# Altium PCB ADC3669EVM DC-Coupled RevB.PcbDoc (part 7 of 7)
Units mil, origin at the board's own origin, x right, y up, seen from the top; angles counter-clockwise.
Board outline 5000 x 2716.54 mil, 12 copper layers (Top Layer, L2 GND, L3 SIG, L4 GND, L5 PWR, L6 GND, L7 GND, L8 PWR, L9 GND, L10 PWR, L11 GND, Bottom Layer), stack 61 mil thick; 546 components, 341 nets, 2088 pads, 1256 vias.
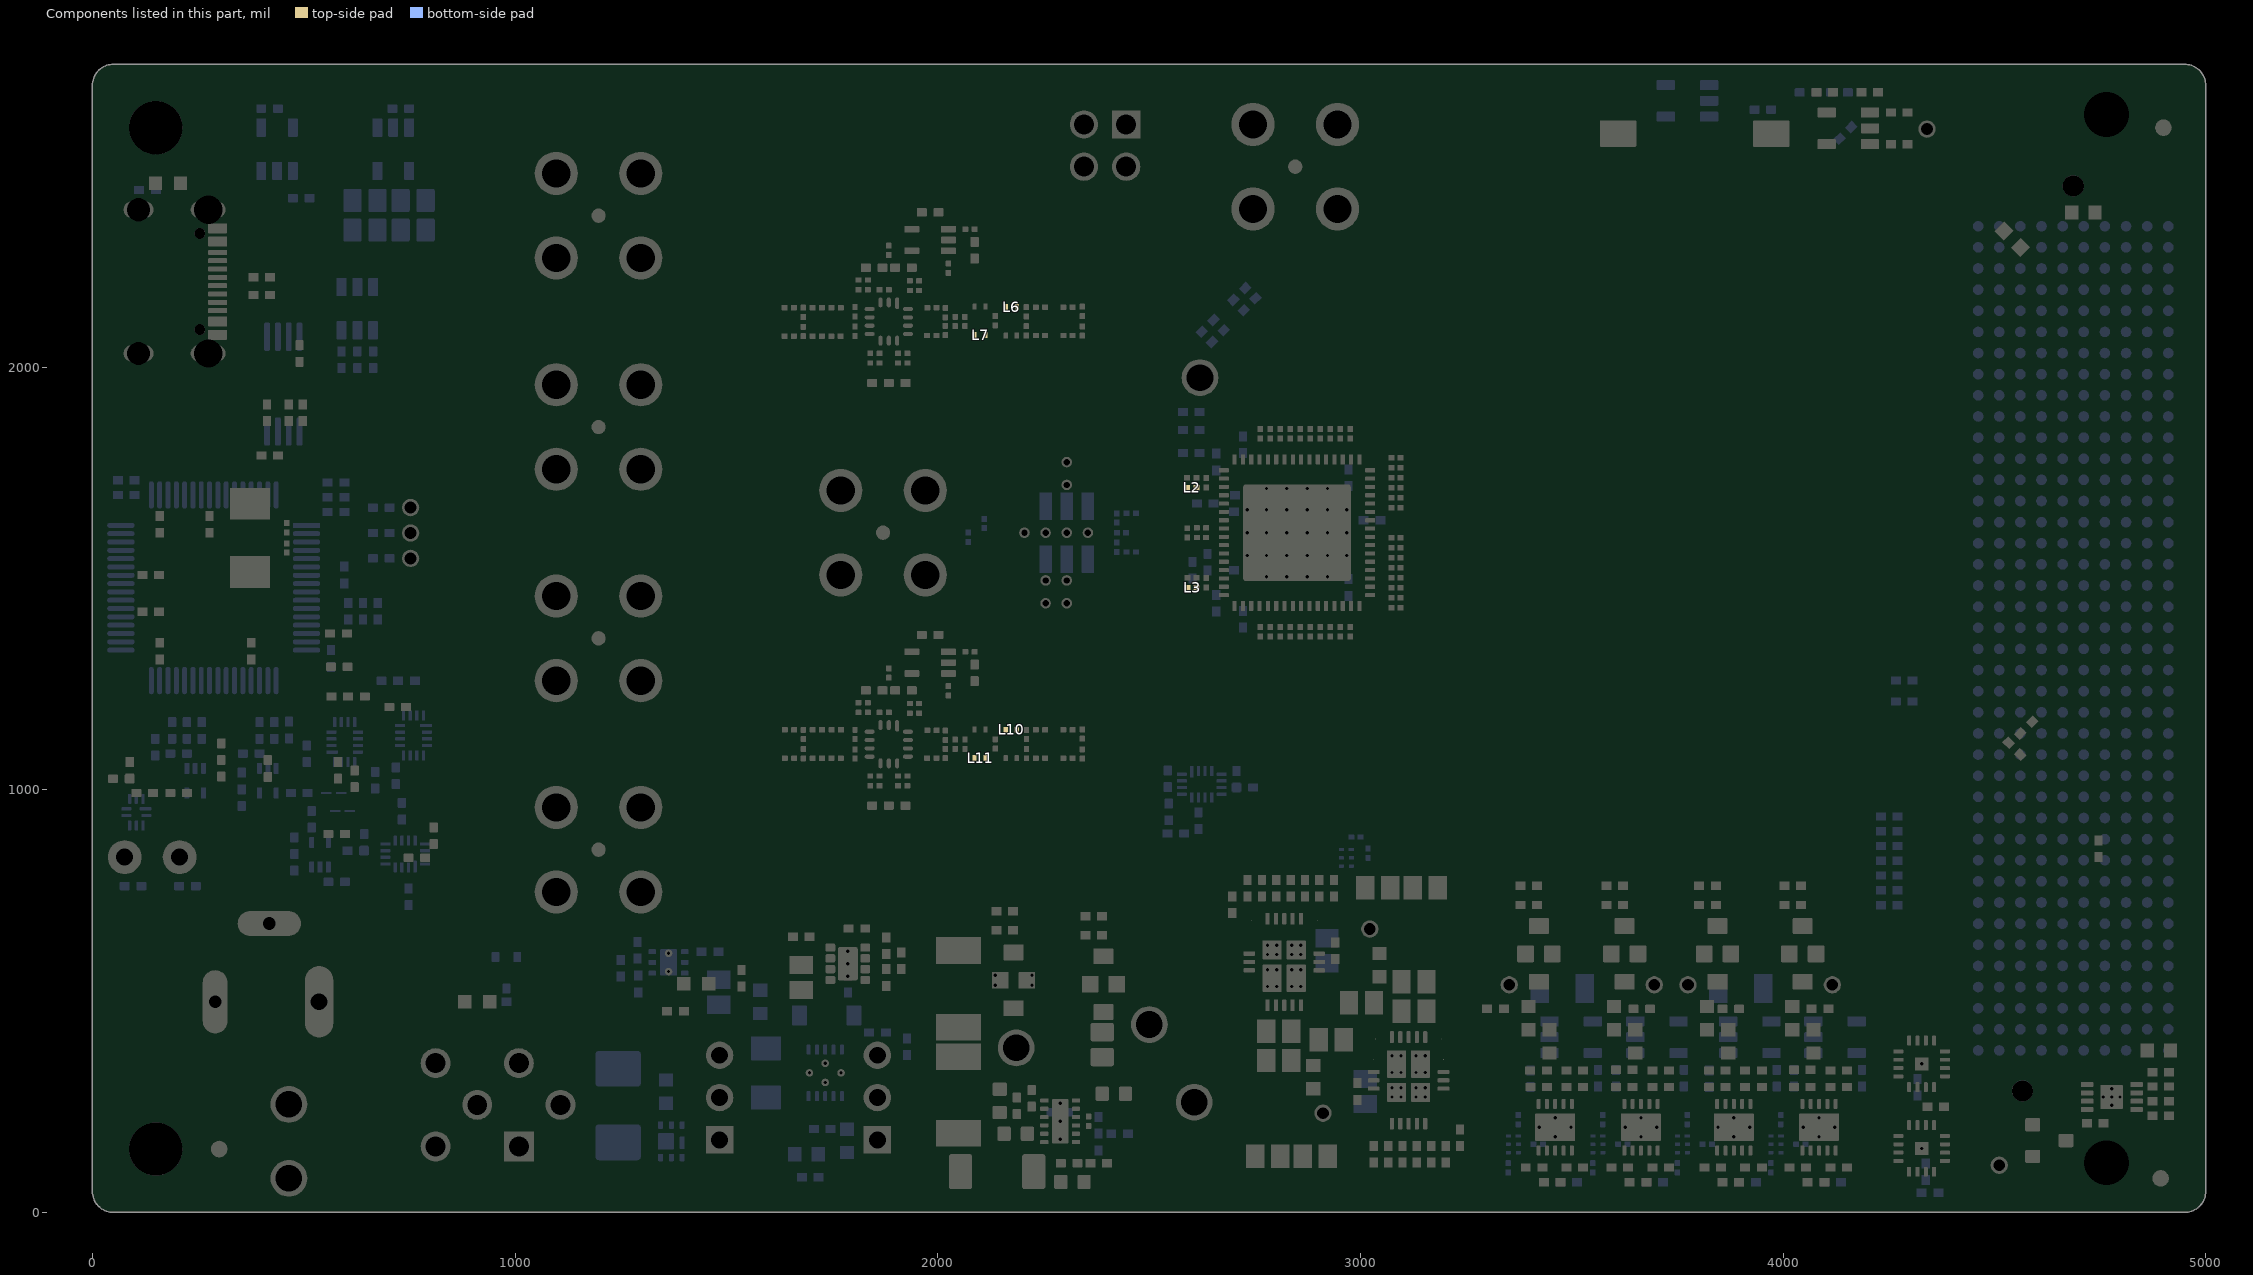
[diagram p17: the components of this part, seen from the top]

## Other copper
Top Layer:
  drawing of 104 lines, arcs and shapes, not listed
  text ".Layer_Name" at 577,-858.49 h60
L2 GND:
  pour cut-out: 1197.57,883.99 ccw(c1197.5,858.27) 1179.31,876.46 ccw(c1196.84,858.93) 1172.05,858.93 1172.05,857.55 ccw(c1196.78,857.55) 1179.3,840.07 1180.01,839.36 ccw(c1197.5,856.85) 1197.5,832.11 1198.2,832.11 ccw(c1198.2,857.57) 1216.2,839.57 1216.34,839.71 ccw(c1198,858.05) 1223.94,858.05 ccw(c1198.01,858.05) 1216.35,876.38 1215.98,876.75 ccw(c1198.5,859.27) 1198.5,883.99
  pour cut-out: 1197.57,1383.99 ccw(c1197.5,1358.27) 1179.31,1376.46 ccw(c1196.84,1358.93) 1172.05,1358.93 1172.05,1357.55 ccw(c1196.78,1357.55) 1179.3,1340.07 1180.01,1339.36 ccw(c1197.5,1356.85) 1197.5,1332.11 1198.2,1332.11 ccw(c1198.2,1357.57) 1216.2,1339.57 1216.34,1339.71 ccw(c1198,1358.05) 1223.94,1358.05 ccw(c1198.01,1358.05) 1216.35,1376.38 1215.98,1376.75 ccw(c1198.5,1359.27) 1198.5,1383.99
  pour cut-out: 1197.57,2383.99 ccw(c1197.5,2358.27) 1179.31,2376.46 ccw(c1196.84,2358.93) 1172.05,2358.93 1172.05,2357.55 ccw(c1196.78,2357.55) 1179.3,2340.07 1180.01,2339.36 ccw(c1197.5,2356.85) 1197.5,2332.11 1198.2,2332.11 ccw(c1198.2,2357.57) 1216.2,2339.57 1216.34,2339.71 ccw(c1198,2358.05) 1223.94,2358.05 ccw(c1198.01,2358.05) 1216.35,2376.38 1215.98,2376.75 ccw(c1198.5,2359.27) 1198.5,2383.99
  pour cut-out: 1197.57,1883.99 ccw(c1197.5,1858.27) 1179.31,1876.46 ccw(c1196.84,1858.93) 1172.05,1858.93 1172.05,1857.55 ccw(c1196.78,1857.55) 1179.3,1840.07 1180.01,1839.36 ccw(c1197.5,1856.85) 1197.5,1832.11 1198.2,1832.11 ccw(c1198.2,1857.57) 1216.2,1839.57 1216.34,1839.71 ccw(c1198,1858.05) 1223.94,1858.05 ccw(c1198.01,1858.05) 1216.35,1876.38 1215.98,1876.75 ccw(c1198.5,1859.27) 1198.5,1883.99
  text ".Layer_Name" at 572,-863.49 h60
L3 SIG:
  pour cut-out: 1197.57,2383.99 ccw(c1197.5,2358.27) 1179.31,2376.46 ccw(c1196.84,2358.93) 1172.05,2358.93 1172.05,2357.55 ccw(c1196.78,2357.55) 1179.3,2340.07 1180.01,2339.36 ccw(c1197.5,2356.85) 1197.5,2332.11 1198.2,2332.11 ccw(c1198.2,2357.57) 1216.2,2339.57 1216.34,2339.71 ccw(c1198,2358.05) 1223.94,2358.05 ccw(c1198.01,2358.05) 1216.35,2376.38 1215.98,2376.75 ccw(c1198.5,2359.27) 1198.5,2383.99
  pour cut-out: 1197.57,883.99 ccw(c1197.5,858.27) 1179.31,876.46 ccw(c1196.84,858.93) 1172.05,858.93 1172.05,857.55 ccw(c1196.78,857.55) 1179.3,840.07 1180.01,839.36 ccw(c1197.5,856.85) 1197.5,832.11 1198.2,832.11 ccw(c1198.2,857.57) 1216.2,839.57 1216.34,839.71 ccw(c1198,858.05) 1223.94,858.05 ccw(c1198.01,858.05) 1216.35,876.38 1215.98,876.75 ccw(c1198.5,859.27) 1198.5,883.99
  pour cut-out: 1197.57,1383.99 ccw(c1197.5,1358.27) 1179.31,1376.46 ccw(c1196.84,1358.93) 1172.05,1358.93 1172.05,1357.55 ccw(c1196.78,1357.55) 1179.3,1340.07 1180.01,1339.36 ccw(c1197.5,1356.85) 1197.5,1332.11 1198.2,1332.11 ccw(c1198.2,1357.57) 1216.2,1339.57 1216.34,1339.71 ccw(c1198,1358.05) 1223.94,1358.05 ccw(c1198.01,1358.05) 1216.35,1376.38 1215.98,1376.75 ccw(c1198.5,1359.27) 1198.5,1383.99
  pour cut-out: 1197.57,1883.99 ccw(c1197.5,1858.27) 1179.31,1876.46 ccw(c1196.84,1858.93) 1172.05,1858.93 1172.05,1857.55 ccw(c1196.78,1857.55) 1179.3,1840.07 1180.01,1839.36 ccw(c1197.5,1856.85) 1197.5,1832.11 1198.2,1832.11 ccw(c1198.2,1857.57) 1216.2,1839.57 1216.34,1839.71 ccw(c1198,1858.05) 1223.94,1858.05 ccw(c1198.01,1858.05) 1216.35,1876.38 1215.98,1876.75 ccw(c1198.5,1859.27) 1198.5,1883.99
  text ".Layer_Name" at 582,-858.49 h60
L6 GND:
  text ".Layer_Name" at 577,-863.49 h60
L7 GND:
  text ".Layer_Name" at 582,-863.49 h60
L10 PWR:
  pour cut-out: 2375.68,1583.41 2375.68,1507.41 2334.68,1507.41 2334.68,1583.41
  pour cut-out: 2375.68,1708.61 2375.68,1632.61 2334.68,1632.61 2334.68,1708.61
  pour cut-out: 2275.68,1708.61 2275.68,1632.61 2234.68,1632.61 2234.68,1708.61
  text ".Layer_Name" at 587,-863.49 h60
L11 GND:
  pour cut-out: 2375.68,1583.41 2375.68,1507.41 2334.68,1507.41 2334.68,1583.41
  pour cut-out: 2375.68,1708.61 2375.68,1632.61 2334.68,1632.61 2334.68,1708.61
  pour cut-out: 2275.68,1708.61 2275.68,1632.61 2234.68,1632.61 2234.68,1708.61
  text ".Layer_Name" at 582,-848.49 h60
Bottom Layer:
  region net 5V: 751,2361.04 750.68,2234.1 628.58,2234.1 ccw(c628.58,2206.78) 602.43,2214.71 602.43,2202.59 cw(c589.45,2202.59) 601.26,2197.19 601.26,2170.7 cw(c598.5,2170.7) 598.5,2167.95 580.43,2167.95 cw(c580.43,2170.75) 577.63,2170.75 577.63,2267.14 cw(c589.45,2267.14) 589.45,2278.95 627.12,2278.95 ccw(c627.12,2304.53) 652.69,2304.53 652.69,2416.96 cw(c657.47,2416.96) 657.47,2421.73 ccw(c657.47,2426.8) 662.54,2426.8 662.54,2483.23 cw(c665.13,2483.23) 665.13,2485.83 683.4,2485.83 cw(c683.4,2483.07) 686.16,2483.07 686.16,2448.08 ccw(c712.5,2448.08) 712.5,2421.73 746.82,2421.73 cw(c746.83,2417.56) 751,2417.56
  region net VCORE: 145.38,1723.44 ccw(c138.9,1723.44) 138.9,1729.92 ccw(c138.9,1724.59) 133.57,1724.59 133.57,1723.49 cw(c117.39,1723.49) 117.39,1707.31 88.3,1707.31 88.3,1687.62 116.18,1687.62 cw(c116.18,1670.19) 133.61,1670.19 ccw(c138.82,1670.19) 138.82,1664.99 139.57,1664.99 ccw(c139.57,1670.8) 145.38,1670.8 145.38,1672.03
  region net GND: 1416.52,120.79 ccw(c1416.52,124.73) 1420.45,124.73 1420.45,180.61 ccw(c1415.8,180.61) 1415.8,185.26 1397.41,185.26 ccw(c1397.41,177.37) 1389.52,177.37 1389.52,129.58 1389.48,129.58 1389.48,123.86 ccw(c1392.54,123.86) 1392.54,120.79
  region net GND: 1644.7,120.67 1682.33,120.67 ccw(c1682.33,127.81) 1689.48,127.81 1689.48,147.73 ccw(c1683.03,147.73) 1683.03,154.13 1644.7,154.13
  region net GND: 1802.04,125.17 1802.04,162.8 ccw(c1794.9,162.8) 1794.9,169.94 1774.99,169.94 ccw(c1774.99,163.5) 1768.58,163.5 1768.58,125.17
  region net GND: 1843.23,442.16 1799.98,442.16 cw(c1799.98,446.1) 1796.04,446.1 1796.04,486.17 cw(c1799.64,486.17) 1799.64,490.19 1843.23,490.19
  region net 1p8V_Utility: 1239.95,546.31 1239.95,569.52 1239.63,569.84 1239.79,570 1242.74,569.93 1272.98,569.93 ccw(c1272.98,571.9) 1274.95,571.9 1324.79,571.9 1331.7,571.9 cw(c1331.7,569.95) 1333.65,569.95 1333.65,562.03 cw(c1331.7,562.03) 1331.7,560.08 1312.45,560.08 ccw(c1312.45,554.79) 1307.15,554.79 cw(c1300.64,554.79) 1300.64,548.27 1261.6,548.27 ccw(c1261.6,546.31) 1259.63,546.31
  region net MainPwr: 1509.49,559.86 1510.13,560.5 1619.61,560.5 1619.61,626.05 1619.77,626.2 1619.14,626.83 1469.12,626.83 1469.12,583.67 cw(c1457.29,583.67) 1458.49,571.9 1401.56,571.9 1394.65,571.9 ccw(c1394.65,569.95) 1392.7,569.95 1392.7,562.03 ccw(c1394.65,562.03) 1394.65,560.08 1409.59,560.08 cw(c1409.59,550.24) 1419.43,550.24 1419.43,543.16 ccw(c1434,543.15) 1434,528.59 1509.49,528.59
  region net NetF2_1: 1044.43,191.72 1044.43,104.43 965,25 657.93,25 532.93,150 447.72,150 398.54,199.18 398.54,563.64 448.13,613.23 615.09,613.23 703.35,524.97 703.35,142.62 748.06,97.91 876.41,97.91 970.22,191.72 980.26,191.72
  region net GND: 2565.6,1017.07 2589.22,1017.07 2589.22,1040.69 2565.6,1040.69 2565.6,1022.32
  region net VADJ: 775.62,820.51 799.24,820.51 799.24,844.13 775.62,844.13 775.62,825.75
  region net VADJ: 775.62,836.26 799.24,836.26 799.24,859.88 775.62,859.88 775.62,841.5
  region net 3p3V_Utility: 585.07,1077.32 585.07,1053.7 608.69,1053.7 608.69,1077.32 590.31,1077.32
  region net 3p3V_Utility: 569.32,1077.32 569.32,1053.7 592.94,1053.7 592.94,1077.32 574.57,1077.32
  region net NetC2_2: 890.19,413.44 765.73,413.44 763.32,415.86 763.32,215.14 1088.49,215.14 1182.48,121.15 1372.56,121.15 1375.72,124.31 1375.72,274.06 1178.53,274.06 1160,292.59 890.98,292.59
  region net NetC2_1: 922.5,414 922.5,312.51 1181.03,312.51 1196.05,297.5 1379.68,297.5 1389.5,287.68 1389.5,197.92 1421.45,197.92 1421.45,300.48 1442.88,321.9 1527.55,321.9 1535.52,329.87 1535.52,400.36 1521,414
  region net NetF1_2: 1627.93,300.48 1641.5,286.9 1738.53,286.9 1738.53,264.76 1718.79,245.02 1718.79,187.41 1695.16,187.41 1651.84,230.74 1456.25,230.74 1437.1,249.89 1437.1,292.59 1454.51,310 1525.03,309.92 1534.46,300.48
  region net NetC3_2: 1748.83,281.94 1748.85,281.93 1748.85,256.92 1733.87,241.94 1734.53,241.27 1734.53,187.77 1701.27,154.5 1701.27,97.91 1706.33,92.84 1706.33,73.16 1729.81,73.16 1732.76,76.11 1732.76,154.5 1758.16,179.89 1758.16,281.74 1758.28,281.86
  region net NetC4_2: 1768.52,284.03 1769.48,283.06 1769.48,180.36 1800.67,180.36 1800.98,180.66 1800.98,243.73 1777.96,266.75 1777.96,283.57
  region net NetD4_1: 1641.93,373.64 1627.87,359.58 1558.17,359.58 1558.17,489.91 1738.53,489.91 1738.53,373.64
  pour cut-out: 2375.68,1708.61 2375.68,1632.61 2334.68,1632.61 2334.68,1708.61
  pour cut-out: 2275.68,1708.61 2275.68,1632.61 2234.68,1632.61 2234.68,1708.61
  pour cut-out: 2375.68,1583.41 2375.68,1507.41 2334.68,1507.41 2334.68,1583.41
  text ".Layer_Name" at 577,-858.49 h60
Multi-Layer:
  pour cut-out: 1870.66,1633.99 ccw(c1870.59,1608.27) 1852.4,1626.46 ccw(c1869.93,1608.93) 1845.14,1608.93 1845.14,1607.55 ccw(c1869.87,1607.55) 1852.38,1590.07 1853.09,1589.36 ccw(c1870.59,1606.85) 1870.59,1582.11 1871.29,1582.11 ccw(c1871.29,1607.57) 1889.29,1589.57 1889.43,1589.71 ccw(c1871.09,1608.05) 1897.03,1608.05 ccw(c1871.1,1608.05) 1889.43,1626.38 1889.07,1626.75 ccw(c1871.59,1609.27) 1871.59,1633.99

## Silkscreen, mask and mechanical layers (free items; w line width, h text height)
Top Overlay:
  circle w10: c3034.96,1816.84 r4.89
  text "ADC3669EVM-DC / DC-Coupled / LMH5401 / Rev B" at 3456.09,1774.18 h60
  text "12V 1A" at 35.49,328.46 h50
  text ".Layer_Name" at 577,-858.49 h60
Bottom Overlay:
  text "VCM" at 2550.34,1951.27 h50
  text "12V / FMC" at 4661.42,46.52 h40
  text ".Layer_Name" at 577,-858.49 h60
Top Paste:
  text ".Layer_Name" at 577,-858.49 h60
Bottom Paste:
  text ".Layer_Name" at 577,-858.49 h60
Top Solder:
  text ".Layer_Name" at 577,-858.49 h60
  text ".Layer_Name" at 577,-858.49 h60
Bottom Solder:
  text ".Layer_Name" at 577,-858.49 h60
Drill Guide:
  text ".Layer_Name" at 577,-858.49 h60
M1 Board Outline:
  lines w10: 0,50 ccw(c50,50) 50,0 4950,0 ccw(c4950,50) 5000,50 5000,2616.53 5000,2666.54 ccw(c4950,2666.54) 4950,2716.54 50,2716.54 ccw(c50,2666.54) 0,2666.54 ; 0,50 0,50 ; 0,50 0,2666.53 ; 0,2666.53 0,2666.54
  text ".Layer_Name" at 577,-858.49 h60
M2 Board Dimensions:
  rectangle: 125,-400 500,-275
  rectangle: 0,-275 125,-150
  lines w7: 0,-275 1000,-275 ; 125,-400 125,-150 ; 250,-400 250,-150 ; 500,-400 500,-150 ; 750,-400 750,-150 ; 0,-400 0,-150 1000,-150 1000,-400 0,-400
  text ".Layer_Name" at 577,-858.49 h60
M3 3D STEP Top:
  text ".Layer_Name" at 577,-858.49 h60
M4 3D STEP Bottom:
  text ".Layer_Name" at 577,-858.49 h60
M5 Assembly Top:
  circle w10: c1616.28,1894.8 r4
  lines w10: -292,-930.17 6308,-930.17 ; -292,-726.83 6310,-726.83 ; -292,-523.5 -292,-1133.5 3713,-1133.5 6310,-1133.5 6310,-523.5 -291.5,-523.5 -291.5,-1133.5 1284,-1133.5 ; 2173,-1133.5 2173,-523.5 ; 3440,-726.83 3440,-523.5 ; 4280,-726.83 4280,-523.5 ; 4902,-1140 4902,-937.17
  text "COMPONENTS MARKED 'DNP' SHOULD NOT BE POPULATED." at 1153.5,-318.5 h60
  text "ASSEMBLY VARIANT:" at 1153,-434 h60
  text ".VariantName" at 2189,-434 h60
  text "PCB VIEWED FROM TOP SIDE" at -228.5,-655.67 h60
  text "BOARD #:" at 2248,-655.67 h60
  text ".PRJ_Number" at 2793.5,-655.67 h60
  text "REV:" at 3638,-655.67 h60
  text ".PCB_Rev" at 3929.5,-655.67 h60
  text "SVN REV:" at 4476,-655.67 h60
  text ".VersionControl_RevNumber" at 4982,-655.67 h60
  text "PLOT NAME =" at -228.5,-1064.34 h60
  text ".plot_File_Name" at 577,-1064.34 h60
  text "GENERATED    :" at 2250,-1064.34 h60
  text ".Print_Date" at 3119.5,-1064.34 h60
  text ".Print_Time" at 3848.5,-1064.34 h60
  text "TEXAS INSTRUMENTS" at 5113,-1064.34 h60
M6 Assembly Bottom:
  lines w10: -292.5,-727.33 6309.5,-727.33 ; -290.5,-930.67 6309.5,-930.67 ; 1115.5,-1140.5 1115.5,-937.67 ; 1737.5,-727.33 1737.5,-524 ; 2577.5,-727.33 2577.5,-524 ; 3844.5,-1134 3844.5,-524 ; 4733.5,-1134 6309,-1134 6309,-524 -292.5,-524 -292.5,-1134 2304.5,-1134 6309.5,-1134 6309.5,-524
  text "COMPONENTS MARKED 'DNP' SHOULD NOT BE POPULATED." at 6102,-318 h60
  text ".VariantName" at 5058,-434 h60
  text "ASSEMBLY VARIANT:" at 6097,-434 h60
  text ".VersionControl_RevNumber" at 1035.5,-656.17 h60
  text "SVN REV:" at 1541.5,-656.17 h60
  text ".PCB_Rev" at 2088,-656.17 h60
  text "REV:" at 2379.5,-656.17 h60
  text ".PRJ_Number" at 3224,-656.17 h60
  text "BOARD #:" at 3769.5,-656.17 h60
  text "PCB VIEWED FROM BOTTOM SIDE" at 6246,-656.17 h60
  text "TEXAS INSTRUMENTS" at 904.5,-1064.84 h60
  text ".Print_Time" at 2169,-1064.84 h60
  text ".Print_Date" at 2898,-1064.84 h60
  text "GENERATED    :" at 3767.5,-1064.84 h60
  text ".plot_File_Name" at 5440.5,-1064.84 h60
  text "PLOT NAME =" at 6246,-1064.84 h60
M9 Title Sheet:
  drawing of 56 lines, arcs and shapes, not listed
  text "1" at 1058.34,13381.39 h70
  text "2" at 4384,13381.39 h70
  text "3" at 7714,13381.39 h70
  text "4" at 11049,13381.39 h70
  text "5" at 14374,13381.39 h70
  text "6" at 17709,13381.39 h70
  text "A" at -463,11603.39 h70
  text "A" at 19237,11603.39 h70
  text "B" at -463,7853.39 h70
  text "B" at 19237,7853.39 h70
  text "C" at -463,4103.39 h70
  text "C" at 19237,4103.39 h70
  text "D" at -463,353.39 h70
  text "D" at 19237,353.39 h70
  text "PROJECT TITLE:" at 16143,268.39 h45
  text ".PRJ_Title" at 16193,135.06 h70
  text "DESIGNED FOR:" at 16143,-32.61 h45
  text ".PRJ_Customer" at 16193,-172.61 h70
  text "FILE NAME:" at 16143,-332.61 h45
  text ".PCB_File_Name_No_Path" at 16193,-452.61 h70
  text "Texas Instruments (TI) and/or its licensors do not warrant the accuracy or completeness of this specification" at 11173.5,-614.45 h45
  text "ENGINEER:" at 16143,-622.61 h45
  text "LAYOUT BY:" at 17648,-622.61 h45
  text "or any information contained therein. TI and/or its licensors do not warrant that this design will meet" at 11128.51,-727.11 h45
  text ".PRJ_Engineer" at 16193,-777.6 h70
  text ".PCB_Layout" at 17698.5,-777.6 h70
  text "the specifications, will be suitable for your application or fit for any particular purpose, or will operate in" at 11128.51,-839.78 h45
  text ".Layer_Name" at 577,-858.49 h60
  text "ALTIUM DESIGNER VERSION:" at 17648,-932.61 h45
  text "an implementation. TI and/or its licensors do not warrant that the design is production worthy. You should" at 11128.51,-952.44 h45
  text "completely validate and test your design implementation to confirm the system functionality for your application." at 11173.5,-1065.11 h45
  text ".print_Scale" at 16193,-1065.94 h70
  text ".Application_BuildNumber" at 17698.5,-1065.94 h70
  text "1" at 1058.34,-1318.61 h70
  text "2" at 4384,-1318.61 h70
  text "3" at 7714,-1318.61 h70
  text "4" at 11049,-1318.61 h70
  text "5" at 14374,-1318.61 h70
  text "6" at 17709,-1318.61 h70
M10 Fab Notes:
  drawing of 209 lines, arcs and shapes, not listed
  text "M10 Fab Notes" at 16103.69,8035.93 h60
  text "DESIGN INFORMATION" at 17182.02,7918.81 h60
  text "MIN. TRACK WIDTH:" at 16537.46,7786.68 h60
  text "4" at 17633.7,7786.68 h60
  text "MIL" at 17788.46,7786.68 h60
  text "MIN. CLEARANCE:" at 16537.46,7662.55 h60
  text "MIL" at 17788.46,7662.55 h60
  text "5" at 17633.92,7660.91 h60
  text "MIN. VIA PAD SIZE:" at 16537.46,7538.43 h60
  text "18" at 17603.71,7538.43 h60
  text "MIL" at 17788.46,7538.43 h60
  text "0.05mm (2MIL)" at 17232.46,7408.53 h60
  text "MINIMUM ANNULAR RING" at 16208.23,7400.31 h60
  text "EXTERNAL" at 17940.46,7400.31 h60
  text "PER" at 16408.23,7290.18 h60
  text "IPC-D-275 CLASS 2 LEVEL C" at 16628.23,7290.18 h60
  text "MIL, HOLES" at 18116.46,7189.7 h60
  text "+/-" at 17724,7181.11 h60
  text "+/-" at 18578,7181.11 h60
  text "REGISTRATION TOLERANCES:" at 16208.23,7180.05 h60
  text "METAL" at 17408,7180.05 h60
  text "5" at 17984.2,7180.05 h60
  text "3" at 18817.2,7180.05 h60
  text "MIL" at 18933.46,7180.05 h60
  text "HOLE SIZE TOLERANCE (UNLESS OTHERWISE SPECIFIED):" at 16208.23,7081.73 h60
  text "+/-" at 18578,7078.86 h60
  text "3" at 18817.2,7077.8 h60
  text "MIL" at 18933.46,7077.8 h60
  text "MATERIAL:" at 16133.46,6940.15 h60
  text "UNIFORM STACKUP" at 17867.51,6845.23 h60
  text "HYBRID STACKUP" at 16841.98,6837.95 h60
  text "X" at 17730,6830 h60
  text "FR4-408" at 16548.18,6674.31 h60
  text "X" at 16404,6667.3 h60
  text "Megtron 4    Isola I-Speed" at 16539.43,6473.06 h60
  text "OR" at 16989.42,6473.06 h60
  text "Megtron6    Isola MT-40    Nelco MW-1000" at 16539.43,6276.21 h60
  text "OR" at 16940.78,6276.21 h60
  text "OR" at 17639.51,6276.21 h60
  text "OTHER" at 16579.43,6079.36 h60
  text "X" at 16756.89,5882.87 h60
  text "62 MIL (1.6mm) +/-10%" at 16877.71,5881.78 h60
  text "92 MIL  +/-10%" at 18453.68,5881.78 h60
  text "THICKNESS:" at 16211.38,5873.55 h60
  text "OTHER" at 18162.61,5873.55 h60
  text "TOLERANCE:" at 16211.38,5735.24 h60
  text "X" at 17059.61,5735.24 h60
  text "ANSI IPC-6012 TYPE 3 CLASS 2" at 17237.62,5735.24 h60
  text "OTHER +/-" at 17237.61,5591.05 h60
  text "BOW & TWIST:" at 16211.38,5445.86 h60
  text "X" at 17059.61,5445.86 h60
  text "ANSI IPC-6012 TYPE 3 CLASS 2" at 17237.62,5445.86 h60
  text "OTHER +/-" at 17237.61,5299.17 h60
  text "DRILLING:" at 16136.61,5168.55 h60
  text "NC_DRILL FILES" at 17897.61,5063.36 h60
  text "REFERENCE:" at 16211.38,5059.42 h60
  text "X" at 16868.61,5059.32 h60
  text "AS SHOWN" at 17046.61,5059.42 h60
  text "X" at 17769.61,5059.42 h60
  text "OTHER" at 18195.61,4917.17 h60
  text "PTH COPPER THICKNESS:" at 16211.05,4913.64 h60
  text "X" at 17350.29,4913.64 h60
  text "20-30 um" at 17478.29,4913.64 h60
  text "BOARD FINISH:" at 16136.61,4766.04 h60
  text "SILKSCREEN:" at 16291.83,4655.92 h60
  text "X" at 17249.61,4655.92 h60
  text "TOP" at 17366.61,4655.92 h60
  text "X" at 17759.61,4655.92 h60
  text "BOTTOM" at 17877.61,4655.92 h60
  text "SILKSCREEN COLOR:" at 16291.83,4500.73 h60
  text "X" at 17249.61,4500.73 h60
  text "WHITE" at 17366.61,4500.73 h60
  text "OTHER" at 17877.61,4500.73 h60
  text "RED" at 18483.4,4363.41 h60
  text "X" at 17972.29,4360.69 h60
  text "GREEN" at 17497.61,4357.28 h60
  text "OTHER" at 18115.61,4357.28 h60
  text "SOLDER RESIST COLOR:" at 16291.83,4350.41 h60
  text "X" at 17379.61,4203.03 h60
  text "MATTE" at 17497.61,4203.03 h60
  text "SEMI-GLOSS" at 18115.15,4202.39 h60
  text "X" at 17009.84,4030.26 h60
  text "IMMERSION GOLD (ENIG)" at 17197.61,4030.26 h60
  text "ENEPIG" at 18535.15,4023.03 h60
  text "SURFACE FINISH:" at 16136.61,4022.03 h60
  text "IMM. TIN/SILVER OR EQUIV" at 16466.15,3884.72 h60
  text "HARD GOLD (30u)" at 17897.61,3880.78 h60
  text "OTHER" at 16491.15,3683.93 h60
  text "ARRAY/PANEL:" at 16136.61,3528.55 h60
  text "X" at 17015,3520 h60
  text "CUT AND TRIM PER M1 BOARD OUTLINE" at 17197.61,3520.33 h60
  text "N.C. ROUTE" at 17197.61,3384.36 h60
  text "V. SCORE" at 18063.61,3384.36 h60
  text "CERTIFICATION:" at 16136.61,3255.24 h60
  text "MATERIALS AND WORKMANSHIP FOR ALL PCBS" at 16861.61,3255.24 h60
  text "TO MEET OR EXCEED THE REQUIREMENTS OF:" at 16861.61,3161.18 h60
  text "X" at 16499.12,3032.55 h60
  text "ANSI IPC-A-600F CLASS ->" at 16627.11,3032.55 h60
  text "X" at 18275.12,3032.55 h60
  text "2" at 18385.11,3032.55 h60
  text "1" at 18070.11,3031.05 h60
  text "3" at 18739.11,3031.05 h60
  text "X" at 17311.12,2884.86 h60
  text "RoHS" at 17439.11,2884.86 h60
  text "OTHER" at 18083.51,2884.86 h60
  text "PER ORDER" at 18480.57,2884.86 h60
  text "ALL BOARDS MUST MEET OR EXCEED UL94-V0 REQUIREMENTS." at 16164.15,2731.03 h60
  text "PCB MUST BEAR THE UL94V-0 UL REGISTERED MATERIAL ID NUMBER" at 16164.15,2614.97 h60
  text "ADDITIONAL REQUIREMENTS:" at 16136.61,2445.55 h60
  text "MICROSECTION:" at 16211.38,2338.42 h60
  text "YES" at 17117.11,2338.42 h60
  text "REQUIRED" at 17978.61,2194.09 h60
  text "BARE BOARD ELEC. TEST:" at 16211.38,2191.23 h60
  text "NONE" at 17517.11,2191.23 h60
  text "X" at 17860.61,2191.23 h60
  text "PER ORDER" at 18570.61,2191.23 h60
  text "X" at 16255.91,1999.02 h60
  text "16 MIL & SMALLER VIAS REQUIRE NON-CONDUCTIVE FILL AND PLANARIZE" at 16363.45,1910.22 h59
  text "X" at 16256.89,1799.39 h60
  text "OUTER LAYER TRACKS 9 MIL WIDE REQUIRE 50 OHM SINGLE-ENDED IMPEDANCE" at 16366.4,1699.59 h60
  text "X" at 16255.91,1595.47 h60
  text "OUTER LAYER TRACKS 6 MIL WIDE WITH 4 MIL AIR GAP REQUIRE 100 OHM DIFFERENTIAL IMPEDANCE" at 16366.4,1494.87 h60
  text "INNER LAYER XX & XX TRACKS XX MIL WIDE REQUIRE 50 OHM SINGLE-ENDED IMPEDANCE" at 16366.4,1290.14 h60
  text "INNER LAYER TRACKS XX MIL WIDE WITH   / XX MIL SPACE REQUIRE 100 OHM DIFFERENTIAL IMPEDANCE" at 16360.5,1096.25 h60
  text ".Layer_Name" at 577,-858.49 h60
M11 Gerber Information:
  lines w10: -292,-930.17 6308,-930.17 ; -292,-726.83 6310,-726.83 ; -292,-523.5 -292,-1133.5 3713,-1133.5 6310,-1133.5 6310,-523.5 -291.5,-523.5 -291.5,-1133.5 1284,-1133.5 ; 2173,-1133.5 2173,-523.5 ; 3440,-726.83 3440,-523.5 ; 4280,-726.83 4280,-523.5 ; 4902,-1140 4902,-937.17
  text "ALL ARTWORK VIEWED FROM TOP SIDE" at -228.5,-655.67 h60
  text "BOARD #:" at 2248,-655.67 h60
  text ".PRJ_Number" at 2793.5,-655.67 h60
  text "REV:" at 3638,-655.67 h60
  text ".PCB_Rev" at 3929.5,-655.67 h60
  text "SVN REV:" at 4476,-655.67 h60
  text ".VersionControl_RevNumber" at 4982,-655.67 h60
  text "LAYER NAME =" at -228.5,-858.49 h60
  text "PLOT NAME =" at -228.5,-1064.34 h60
  text ".plot_File_Name" at 577,-1064.34 h60
  text "GENERATED    :" at 2250,-1064.34 h60
  text ".Print_Date" at 3119.5,-1064.34 h60
  text ".Print_Time" at 3848.5,-1064.34 h60
  text "TEXAS INSTRUMENTS" at 5113,-1064.34 h60
M12 Stackup:
  drawing of 763 lines, arcs and shapes, not listed
  text "Layer" at 9956.79,4031.7 h60
  text "Name" at 10366.7,4031.7 h60
  text "Material" at 11296.44,4031.7 h60
  text "Thickness" at 12156.21,4031.7 h60
  text "Constant" at 12806.04,4031.7 h60
  text "Board Layer Stack" at 13375.91,4031.7 h60
  text "Top Overlay" at 10366.7,3911.7 h60
  text "Top Solder" at 10366.7,3791.7 h60
  text "Solder Resist" at 11296.44,3791.7 h60
  text "0.40mil" at 12156.21,3791.7 h60
  text "3.5" at 12806.04,3791.7 h60
  text "1" at 9956.79,3671.7 h60
  text "Top Layer" at 10366.7,3671.7 h60
  text "1.40mil" at 12156.21,3671.7 h60
  text "Dielectric 1" at 10366.7,3551.7 h60
  text "FR408HR" at 11296.44,3551.7 h60
  text "4.50mil" at 12156.21,3551.7 h60
  text "3.54" at 12806.04,3551.7 h60
  text "2" at 9956.79,3431.7 h60
  text "L2 GND" at 10366.7,3431.7 h60
  text "CF-004" at 11296.44,3431.7 h60
  text "1.40mil" at 12156.21,3431.7 h60
  text "Dielectric 3" at 10366.7,3311.7 h60
  text "FR408HR" at 11296.44,3311.7 h60
  text "3.20mil" at 12156.21,3311.7 h60
  text "3.54" at 12806.04,3311.7 h60
  text "3" at 9956.79,3191.7 h60
  text "L3 SIG" at 10366.7,3191.7 h60
  text "CF-004" at 11296.44,3191.7 h60
  text "1.40mil" at 12156.21,3191.7 h60
  text "Dielectric 9" at 10366.7,3071.7 h60
  text "FR408HR" at 11296.44,3071.7 h60
  text "3.20mil" at 12156.21,3071.7 h60
  text "3.54" at 12806.04,3071.7 h60
  text "4" at 9956.79,2951.7 h60
  text "L4 GND" at 10366.7,2951.7 h60
  text "CF-004" at 11296.44,2951.7 h60
  text "1.40mil" at 12156.21,2951.7 h60
  text "Dielectric 7" at 10366.7,2831.7 h60
  text "FR408HR" at 11296.44,2831.7 h60
  text "3.20mil" at 12156.21,2831.7 h60
  text "3.54" at 12806.04,2831.7 h60
  text "5" at 9956.79,2711.7 h60
  text "L5 PWR" at 10366.7,2711.7 h60
  text "CF-004" at 11296.44,2711.7 h60
  text "1.40mil" at 12156.21,2711.7 h60
  text "Dielectric 5" at 10366.7,2591.7 h60
  text "FR408HR" at 11296.44,2591.7 h60
  text "3.20mil" at 12156.21,2591.7 h60
  text "3.54" at 12806.04,2591.7 h60
  text "6" at 9956.79,2471.7 h60
  text "L6 GND" at 10366.7,2471.7 h60
  text "CF-004" at 11296.44,2471.7 h60
  text "1.40mil" at 12156.21,2471.7 h60
  text "Dielectric 11" at 10366.7,2351.7 h60
  text "FR408HR" at 11296.44,2351.7 h60
  text "3.20mil" at 12156.21,2351.7 h60
  text "3.54" at 12806.04,2351.7 h60
  text "Dielectric1" at 10366.7,2231.7 h60
  text "FR408HR" at 11296.44,2231.7 h60
  text "3.20mil" at 12156.21,2231.7 h60
  text "3.54" at 12806.04,2231.7 h60
  text "Dielectric 12" at 10366.7,2111.7 h60
  text "FR408HR" at 11296.44,2111.7 h60
  text "3.20mil" at 12156.21,2111.7 h60
  text "3.54" at 12806.04,2111.7 h60
  text "7" at 9956.79,1991.7 h60
  text "L7 GND" at 10366.7,1991.7 h60
  text "CF-004" at 11296.44,1991.7 h60
  text "1.40mil" at 12156.21,1991.7 h60
  text "Dielectric 6" at 10366.7,1871.7 h60
  text "FR408HR" at 11296.44,1871.7 h60
  text "3.20mil" at 12156.21,1871.7 h60
  text "3.54" at 12806.04,1871.7 h60
  text "8" at 9956.79,1751.7 h60
  text "L8 PWR" at 10366.7,1751.7 h60
  text "CF-004" at 11296.44,1751.7 h60
  text "1.40mil" at 12156.21,1751.7 h60
  text "Dielectric 8" at 10366.7,1631.7 h60
  text "FR408HR" at 11296.44,1631.7 h60
  text "3.20mil" at 12156.21,1631.7 h60
  text "3.54" at 12806.04,1631.7 h60
  text "9" at 9956.79,1511.7 h60
  text "L9 GND" at 10366.7,1511.7 h60
  text "CF-004" at 11296.44,1511.7 h60
  text "1.40mil" at 12156.21,1511.7 h60
  text "Dielectric 10" at 10366.7,1391.7 h60
  text "FR408HR" at 11296.44,1391.7 h60
  text "3.20mil" at 12156.21,1391.7 h60
  text "3.54" at 12806.04,1391.7 h60
  text "10" at 9956.79,1271.7 h60
  text "L10 PWR" at 10366.7,1271.7 h60
  text "CF-004" at 11296.44,1271.7 h60
  text "1.40mil" at 12156.21,1271.7 h60
  text "Dielectric 4" at 10366.7,1151.7 h60
  text "FR408HR" at 11296.44,1151.7 h60
  text "3.20mil" at 12156.21,1151.7 h60
  text "3.54" at 12806.04,1151.7 h60
  text "11" at 9956.79,1031.7 h60
  text "L11 GND" at 10366.7,1031.7 h60
  text "CF-004" at 11296.44,1031.7 h60
  text "1.40mil" at 12156.21,1031.7 h60
  text "Dielectric 2" at 10366.7,911.7 h60
  text "FR408HR" at 11296.44,911.7 h60
  text "4.50mil" at 12156.21,911.7 h60
  text "3.54" at 12806.04,911.7 h60
  text "12" at 9956.79,791.7 h60
  text "Bottom Layer" at 10366.7,791.7 h60
  text "1.40mil" at 12156.21,791.7 h60
  text "Bottom Solder" at 10366.7,671.7 h60
  text "Solder Resist" at 11296.44,671.7 h60
  text "0.40mil" at 12156.21,671.7 h60
  text "3.5" at 12806.04,671.7 h60
  text "Bottom Overlay" at 10366.7,551.7 h60
  text "Total board thickness:" at 9956.79,431.7 h60
  text "61.80mil" at 12156.21,431.7 h60
  text ".Layer_Name" at 577,-858.49 h60
M13 Component Bodies Top:
  text ".Layer_Name" at 577,-858.49 h60
M14 Component Bodies Bottom:
  text ".Layer_Name" at 577,-858.49 h60
M15 Courtyards Top:
  text ".Layer_Name" at 577,-858.49 h60
M16 Courtyards Bottom:
  text ".Layer_Name" at 577,-858.49 h60
Drill Drawing:
  drawing of 185 lines, arcs and shapes, not listed
  text "Symbol" at 230.04,5030 h48
  text "Count" at 577.95,5030 h48
  text "Hole Size" at 1017.84,5030 h48
  text "Plated" at 1790.95,5030 h48
  text "Hole Type" at 2138.86,5030 h48
  text "Drill Layer Pair" at 2638.73,5030 h48
  text "Via/Pad" at 3645.1,5030 h48
  text "Pad Shape" at 4049,5030 h48
  text "Template" at 4782.12,5030 h48
  text "Description" at 5935.11,5030 h48
  text "Hole Tolerance (+)" at 6514.95,5030 h48
  text "Hole Tolerance (-)" at 7414.69,5030 h48
  text "1" at 577.95,4930 h40
  text "39.76mil (1.010mm)" at 1017.84,4930 h40
  text "PTH" at 1790.95,4930 h40
  text "Slot" at 2138.86,4930 h40
  text "Top Layer - Bottom Layer" at 2638.73,4930 h40
  text "Pad" at 3645.1,4930 h40
  text "Rounded" at 4049,4930 h40
  text "r430_170h101_356r85" at 4782.12,4930 h40
  text "2" at 577.95,4830 h40
  text "25.59mil (0.650mm)" at 1017.84,4830 h40
  text "NPTH" at 1790.95,4830 h40
  text "Round" at 2138.86,4830 h40
  text "Top Layer - Bottom Layer" at 2638.73,4830 h40
  text "Pad" at 3645.1,4830 h40
  text "Rounded" at 4049,4830 h40
  text "c65hn65m65p0" at 4782.12,4830 h40
  text "2" at 577.95,4730 h40
  text "29.92mil (0.760mm)" at 1017.84,4730 h40
  text "PTH" at 1790.95,4730 h40
  text "Slot" at 2138.86,4730 h40
  text "Top Layer - Bottom Layer" at 2638.73,4730 h40
  text "Pad" at 3645.1,4730 h40
  text "Rounded" at 4049,4730 h40
  text "r380_150h76_305r75" at 4782.12,4730 h40
  text "2" at 577.95,4630 h40
  text "50.00mil (1.270mm)" at 1017.84,4630 h40
  text "NPTH" at 1790.95,4630 h40
  text "Round" at 2138.86,4630 h40
  text "Top Layer - Bottom Layer" at 2638.73,4630 h40
  text "Pad" at 3645.1,4630 h40
  text "Rounded" at 4049,4630 h40
  text "c127hn127" at 4782.12,4630 h40
  text "2" at 577.95,4530 h40
  text "55.12mil (1.400mm)" at 1017.84,4530 h40
  text "PTH" at 1790.95,4530 h40
  text "Slot" at 2138.86,4530 h40
  text "Top Layer - Bottom Layer" at 2638.73,4530 h40
  text "Pad" at 3645.1,4530 h40
  text "Rounded Rectangle" at 4049,4530 h40
  text "r100_180h140_60r50m100_180p0" at 4782.12,4530 h40
  text "B" at 208.35,4520.01 h44.44
  text "2" at 577.95,4430 h40
  text "66.93mil (1.700mm)" at 1017.84,4430 h40
  text "PTH" at 1790.95,4430 h40
  text "Slot" at 2138.86,4430 h40
  text "Top Layer - Bottom Layer" at 2638.73,4430 h40
  text "Pad" at 3645.1,4430 h40
  text "Rounded Rectangle" at 4049,4430 h40
  text "r100_210h170_60r50m100_210p0" at 4782.12,4430 h40
  text "2" at 577.95,4330 h40
  text "105.91mil (2.690mm)" at 1017.84,4330 h40
  text "NPTH" at 1790.95,4330 h40
  text "Round" at 2138.86,4330 h40
  text "Top Layer - Bottom Layer" at 2638.73,4330 h40
  text "Pad" at 3645.1,4330 h40
  text "Rounded" at 4049,4330 h40
  text "c0hn269m10" at 4782.12,4330 h40
  text "2" at 577.95,4230 h40
  text "125.98mil (3.200mm)" at 1017.84,4230 h40
  text "NPTH" at 1790.95,4230 h40
  text "Round" at 2138.86,4230 h40
  text "Top Layer - Bottom Layer" at 2638.73,4230 h40
  text "Pad" at 3645.1,4230 h40
  text "Rounded" at 4049,4230 h40
  text "c320hn320m320p0" at 4782.12,4230 h40
  text "6" at 577.95,4130 h40
  text "63.00mil (1.600mm)" at 1017.84,4130 h40
  text "PTH" at 1790.95,4130 h40
  text "Round" at 2138.86,4130 h40
  text "Top Layer - Bottom Layer" at 2638.73,4130 h40
  text "Pad" at 3645.1,4130 h40
  text "Rounded" at 4049,4130 h40
  text "c221h160" at 4782.12,4130 h40
  text "8" at 577.95,4030 h40
  text "40.00mil (1.016mm)" at 1017.84,4030 h40
  text "PTH" at 1790.95,4030 h40
  text "Round" at 2138.86,4030 h40
  text "Top Layer - Bottom Layer" at 2638.73,4030 h40
  text "Pad" at 3645.1,4030 h40
  text "(Mixed)" at 4049,4030 h40
  text "(Mixed)" at 4782.12,4030 h40
  text "10" at 577.95,3930 h40
  text "15.00mil (0.381mm)" at 1017.84,3930 h40
  text "PTH" at 1790.95,3930 h40
  text "Round" at 2138.86,3930 h40
  text "Top Layer - Bottom Layer" at 2638.73,3930 h40
  text "Pad" at 3645.1,3930 h40
  text "Rounded" at 4049,3930 h40
  text "c64h38m0mx0" at 4782.12,3930 h40
  text "A" at 208.35,3920.01 h44.44
  text "10" at 577.95,3830 h40
  text "47.24mil (1.200mm)" at 1017.84,3830 h40
  text "PTH" at 1790.95,3830 h40
  text "Round" at 2138.86,3830 h40
  text "Top Layer - Bottom Layer" at 2638.73,3830 h40
  text "Pad" at 3645.1,3830 h40
  text "(Mixed)" at 4049,3830 h40
  text "(Mixed)" at 4782.12,3830 h40
  text "11" at 577.95,3730 h40
  text "28.00mil (0.711mm)" at 1017.84,3730 h40
  text "PTH" at 1790.95,3730 h40
  text "Round" at 2138.86,3730 h40
  text "Top Layer - Bottom Layer" at 2638.73,3730 h40
  text "Pad" at 3645.1,3730 h40
  text "Rounded" at 4049,3730 h40
  text "c104h71" at 4782.12,3730 h40
  text "24" at 577.95,3630 h40
  text "66.93mil (1.700mm)" at 1017.84,3630 h40
  text "PTH" at 1790.95,3630 h40
  text "Round" at 2138.86,3630 h40
  text "Top Layer - Bottom Layer" at 2638.73,3630 h40
  text "Pad" at 3645.1,3630 h40
  text "Rounded" at 4049,3630 h40
  text "c260h170m260p0" at 4782.12,3630 h40
  text "94" at 577.95,3530 h40
  text "7.87mil (0.200mm)" at 1017.84,3530 h40
  text "PTH" at 1790.95,3530 h40
  text "Round" at 2138.86,3530 h40
  text "Top Layer - Bottom Layer" at 2638.73,3530 h40
  text "Pad" at 3645.1,3530 h40
  text "Rounded" at 4049,3530 h40
  text "(Mixed)" at 4782.12,3530 h40
  text "1259" at 577.95,3430 h40
  text "8.00mil (0.203mm)" at 1017.84,3430 h40
  text "PTH" at 1790.95,3430 h40
  text "Round" at 2138.86,3430 h40
  text "Top Layer - Bottom Layer" at 2638.73,3430 h40
  text "(Mixed)" at 3645.1,3430 h40
  text "Rounded" at 4049,3430 h40
  text "(Mixed)" at 4782.12,3430 h40
  text "1437 Total" at 577.95,3330 h40
  text "Slot definitions :" at 230.04,3226.68 h40
  text "Routed Path Length" at 927.83,3226.68 h40
  text "= Calculated from tool start centre position to tool end centre position." at 1672.27,3226.68 h40
  text "Hole Length" at 927.83,3153.37 h40
  text "= Routed Path Length + Tool Size = Slot length as defined in the PCB layout" at 1399.03,3153.37 h40
  text ".Layer_Name" at 577,-858.49 h60
M17 Embedded Cavity:
  text ".Layer_Name" at 577,-858.49 h60
M18 Embedded Assembly:
  text ".Layer_Name" at 577,-858.49 h60
M19 Embedded Keepout:
  text ".Layer_Name" at 567,-858.49 h60

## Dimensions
0,50 to 5000,50 on M2 Board Dimensions
50,2716.54 to 50,0 on M2 Board Dimensions
0,-400 to 1000,-400 on M2 Board Dimensions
